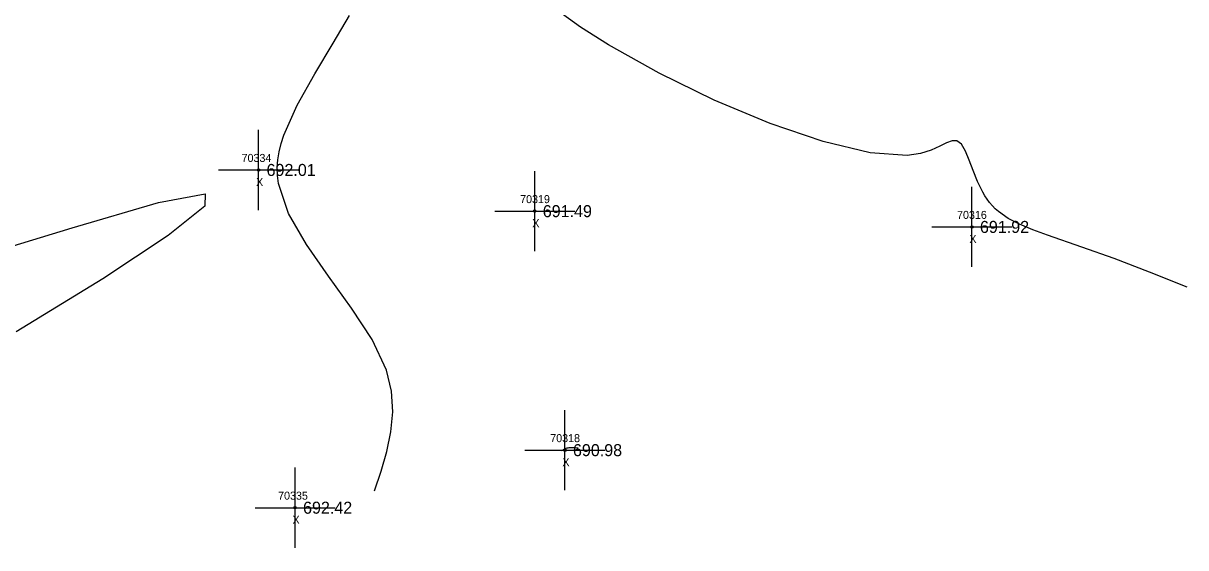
# Model space of a CAD drawing. Extents: x 1376587 to 1378239, y 1000335 to 1003031.
# Drawn here: x 1377010.1 to 1377155.3, y 1001445.5 to 1001510.9 of the extents above; entities that cross this region are included whole.
import ezdxf

# ---------------------------------------------------------------- set-up
doc = ezdxf.new("R2010")
doc.units = 0
for name, color, linetype in [('RD_DTM_Minor1', 7, 'Continuous'), ('RD_EX_Misc', 7, 'Continuous'), ('RD_EX_Misc_txCode', 7, 'Continuous'), ('RD_EX_TX_Misc_ELEV', 7, 'Continuous'), ('RD_SMD_Locator', 7, 'Continuous')]:
    doc.layers.add(name, color=color, linetype=linetype)

msp = doc.modelspace()

# ---------------------------------------------------------------- linework, layer by layer
at = {"layer": 'RD_DTM_Minor1'}
for points in [[(1377155.49, 1001478), (1377150.77, 1001479.88), (1377146.36, 1001481.57), (1377142.34, 1001483.02), (1377138.05, 1001484.49), (1377136.2, 1001485.16), (1377134.55, 1001485.86), (1377133.11, 1001486.6), (1377131.91, 1001487.45), (1377131.51, 1001487.8), (1377131.15, 1001488.18), (1377130.81, 1001488.57), (1377130.5, 1001488.99), (1377130.21, 1001489.42), (1377129.95, 1001489.88), (1377129.31, 1001491.2), (1377128.77, 1001492.57), (1377128.27, 1001493.88), (1377127.79, 1001495), (1377127.28, 1001495.84), (1377126.71, 1001496.28), (1377126.13, 1001496.28), (1377125.44, 1001496.02), (1377124.57, 1001495.59), (1377123.49, 1001495.12), (1377122.16, 1001494.7), (1377120.53, 1001494.45), (1377115.87, 1001494.77), (1377110.01, 1001496.18), (1377103.38, 1001498.45), (1377096.41, 1001501.37), (1377089.54, 1001504.71), (1377083.21, 1001508.25), (1377079.73, 1001510.46), (1377076.73, 1001512.62)], [(1377053.98, 1001452.61), (1377054.8, 1001455.04), (1377055.51, 1001457.49), (1377056.04, 1001459.96), (1377056.27, 1001462.47), (1377056.12, 1001465.03), (1377055.48, 1001467.65), (1377053.67, 1001471.49), (1377051.12, 1001475.41), (1377048.24, 1001479.38), (1377045.48, 1001483.33), (1377043.25, 1001487.21), (1377041.98, 1001490.96), (1377041.86, 1001491.95), (1377041.83, 1001492.93), (1377041.9, 1001493.92), (1377042.06, 1001494.92), (1377042.31, 1001495.94), (1377042.65, 1001496.99), (1377044.32, 1001500.73), (1377046.51, 1001504.64), (1377048.82, 1001508.46), (1377050.84, 1001511.93)], [(1377002.39, 1001481.21), (1377016.24, 1001485.4), (1377027.01, 1001488.58), (1377032.85, 1001489.64), (1377032.77, 1001488.11), (1377028.21, 1001484.44), (1377020.06, 1001479.07), (1377009.21, 1001472.42)], [(1377079.41, 1001457.92), (1377079.09, 1001457.96), (1377078.98, 1001457.97), (1377078.87, 1001457.98), (1377078.77, 1001457.98), (1377078.64, 1001457.98), (1377078.5, 1001457.98), (1377078.37, 1001457.97), (1377078.25, 1001457.95), (1377078.12, 1001457.93), (1377078, 1001457.9), (1377077.89, 1001457.86), (1377077.78, 1001457.81), (1377077.67, 1001457.76), (1377077.56, 1001457.7), (1377077.45, 1001457.64), (1377077.35, 1001457.58)]]:
    msp.add_lwpolyline(points, dxfattribs=at)
at = {"layer": 'RD_EX_Misc'}
for p, q in [((1377039.5, 1001487.64), (1377039.5, 1001497.64)), ((1377034.5, 1001492.64), (1377044.5, 1001492.64)), ((1377074, 1001482.5), (1377074, 1001492.5)), ((1377128.6, 1001480.53), (1377128.6, 1001490.53)), ((1377069, 1001487.5), (1377079, 1001487.5)), ((1377123.6, 1001485.53), (1377133.6, 1001485.53)), ((1377077.77, 1001452.67), (1377077.77, 1001462.67)), ((1377072.77, 1001457.67), (1377082.77, 1001457.67)), ((1377044.06, 1001445.49), (1377044.06, 1001455.49)), ((1377039.06, 1001450.49), (1377049.06, 1001450.49))]:
    msp.add_line(p, q, dxfattribs=at)
at = {"layer": 'RD_SMD_Locator'}
for centre in [(1377039.5, 1001492.64), (1377074, 1001487.5), (1377128.6, 1001485.53), (1377077.77, 1001457.67), (1377044.06, 1001450.49)]:
    msp.add_circle(centre, 0.15, dxfattribs=at)

# ---------------------------------------------------------------- texts
at = {"layer": 'RD_EX_Misc_txCode'}
for s, p in [('70334', (1377037.38, 1001493.64)), ('X', (1377039.19, 1001490.64)), ('70319', (1377072.17, 1001488.5)), ('70316', (1377126.74, 1001486.53)), ('X', (1377073.69, 1001485.5)), ('X', (1377128.28, 1001483.53)), ('70318', (1377075.93, 1001458.67)), ('X', (1377077.45, 1001455.67)), ('70335', (1377041.94, 1001451.49)), ('X', (1377043.74, 1001448.49))]:
    msp.add_text(s, height=1, dxfattribs=at).set_placement(p)
at = {"layer": 'RD_EX_TX_Misc_ELEV'}
for s, p in [('692.01', (1377040.5, 1001491.89)), ('691.49', (1377075, 1001486.75)), ('691.92', (1377129.6, 1001484.78)), ('690.98', (1377078.77, 1001456.92)), ('692.42', (1377045.06, 1001449.74))]:
    msp.add_text(s, height=1.5, dxfattribs=at).set_placement(p)

doc.saveas('drawing.dxf')
